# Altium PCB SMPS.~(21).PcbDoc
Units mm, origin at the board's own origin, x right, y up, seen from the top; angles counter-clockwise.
Board outline 100 x 80 mm, 2 copper layers (Top Layer, Bottom Layer); 139 components, 61 nets, 425 pads, 31 vias.
Unrouted connection lines stored in the file: 313.
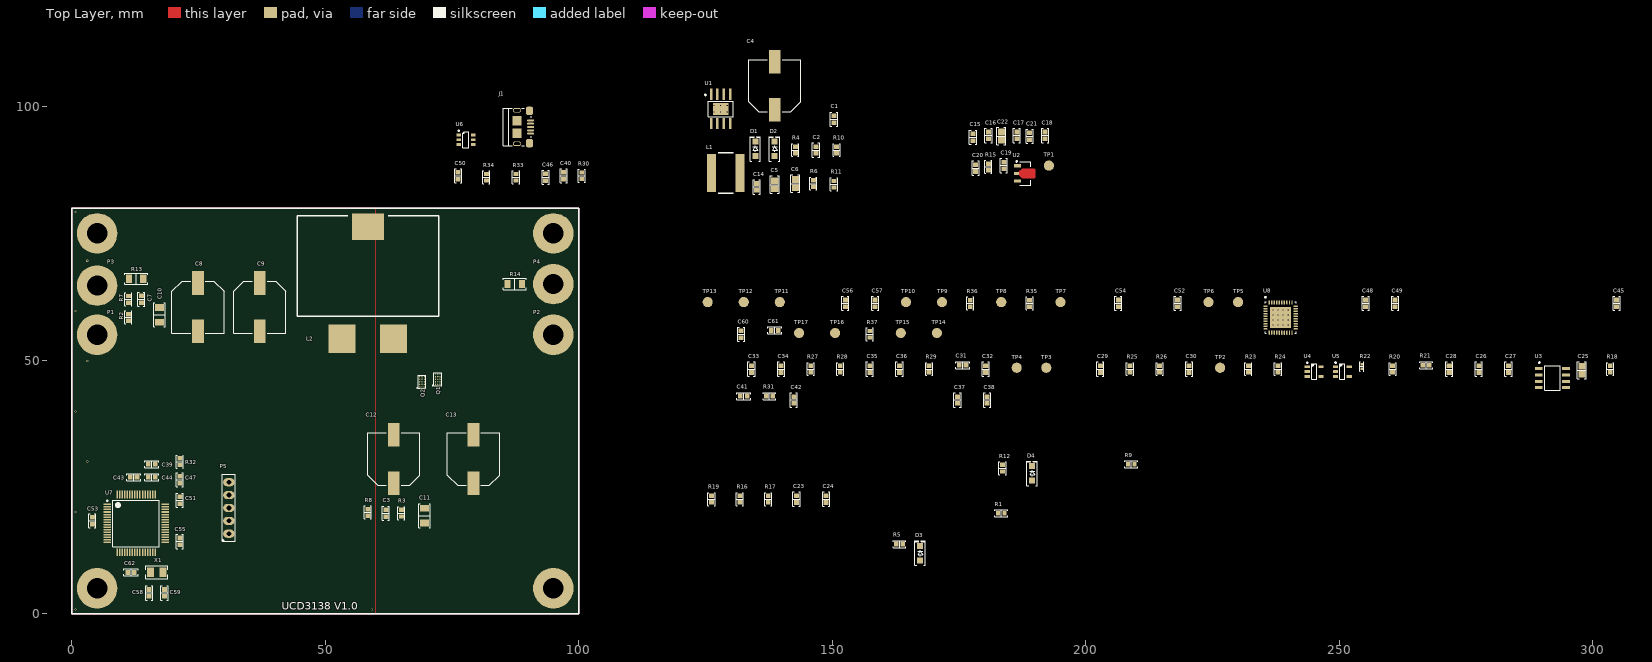
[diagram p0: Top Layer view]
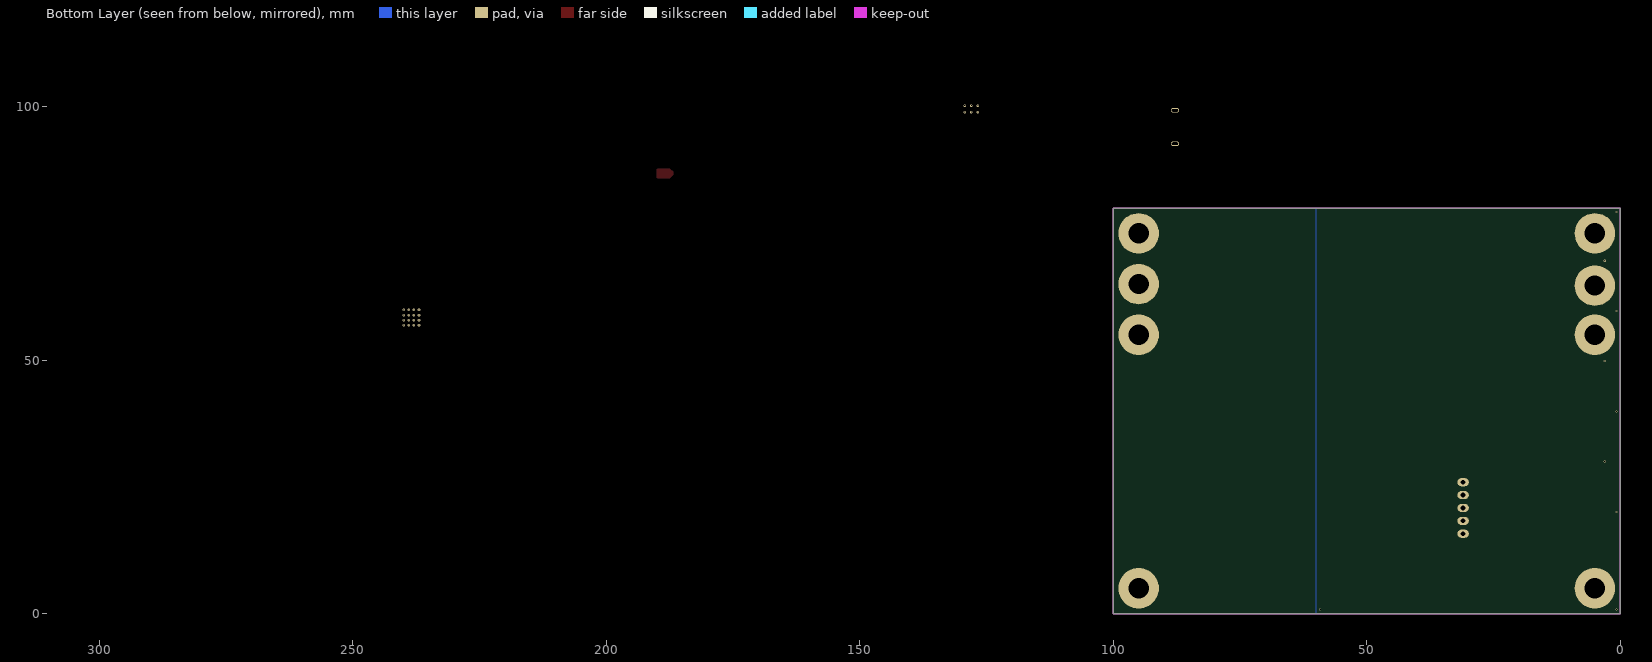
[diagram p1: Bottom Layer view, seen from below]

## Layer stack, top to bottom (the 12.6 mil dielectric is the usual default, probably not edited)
Top Solder: solder mask 0.0102, Solder Resist, Dk 3.5
Top Layer: signal copper 0.0356
Dielectric 1: dielectric 0.32, FR-4, Dk 4.8
Bottom Layer: signal copper 0.0356
Bottom Solder: solder mask 0.0102, Solder Resist, Dk 3.5

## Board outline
0,0 0,80 100,80 100,0

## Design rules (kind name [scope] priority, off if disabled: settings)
Clearance [All] p1: gap=0.254 ignorepadtopadclearanceinfootprint=FALSE except(0: Arc-Hole Track-Hole SMDPad-Hole THPad-Hole Via-Hole Fill-Hole Poly-Hole Region-Hole Text-Hole; 0.178: SMDPad-SMDPad; 0.203: Track-SMDPad; 0.229: Arc-Arc Arc-Track Arc-SMDPad Track-Track; 0.508: THPad-THPad)
ComponentClearance U1 [InComponent('U1')] p1: gap=0.508 collisioncheckmode=3 verticalgap=0 showdistances=TRUE
ComponentClearance [All] p2: gap=0.5 collisioncheckmode=3 verticalgap=0.1 showdistances=TRUE
Height [All] p1: minheight=0 maxheight=50.8 prefheight=12.7
HoleSize [All] p1: absolutevalues=TRUE maxlimit=10 minlimit=0.2 maxpercent=80.000 minpercent=20.000
MinimumSolderMaskSliver [All] p1: minsoldermaskwidth=0.025
PlaneClearance [All] p1: clearance=0.254
PlaneConnect [All] p1: planeconnectstyle=Direct reliefexpansion=0.508 reliefentries=4 reliefconductorwidth=0.508 reliefairgap=0.508
PolygonConnect GND [InNet('GND')] p1: connectstyle=Direct reliefconductorwidth=0.254 reliefentries=4 polygonreliefangle="90 Angle" airgapwidth=0.254
PolygonConnect DirectConnect [All] p2: connectstyle=Direct reliefconductorwidth=0.254 reliefentries=4 polygonreliefangle="90 Angle" airgapwidth=0.254
RoutingVias [All] p1: holewidth=0.2 width=0.8 viastyle="Through Hole" minholewidth=0.2 minwidth=0.4 maxholewidth=0.4 maxwidth=0.8
SilkToSilkClearance [All] p1: silktosilkclearance=0
SolderMaskExpansion [All] p1: expansion=0.102
Width [All] p1: maxlimit=12.7 minlimit=0.254 preferedwidth=0.254
23 further rules are at their usual default settings.

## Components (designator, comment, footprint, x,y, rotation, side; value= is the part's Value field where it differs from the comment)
C1 "10nF" C0603 150.368,97.536 r90 top
C2 "1nF" C0603 146.812,91.44 r90 top
C3 "10nF" C0603 61.976,19.812 r270 top
C4 "47µF 80V" "CAP ALUM 10.3MM" 138.684,104.14 r90 top
C5 "10µF 16V" C0805 138.684,84.62 r90 top
C6 "10µF 16V" C0805 142.748,84.836 r90 top
C7 "10nF" C0603 13.716,61.976 r270 top
C8 "47µF 80V" "CAP ALUM 10.3MM" 24.892,60.452 r270 top
C9 "47µF 80V" "CAP ALUM 10.3MM" 37.084,60.452 r270 top
C10 "1µF 80V" C1206 17.272,58.928 r270 top
C11 "1µF 80V" C1206 69.596,19.304 r270 top
C12 "47µF 80V" "CAP ALUM 10.3MM" 63.5,30.48 r90 top
C13 "47µF 80V" "CAP ALUM 10.3MM" 79.248,30.48 r90 top
C14 "47pF" C0603 135.128,84.161 r90 top
C15 "10µF" C0603 177.8,93.98 r90 top
C16 "100nF" C0603 180.848,94.321 r90 top
C17 "10nF" C0603 186.436,94.321 r90 top
C18 "10µF" C0603 192.024,94.321 r90 top
C19 "100nF" C0603 183.896,88.392 r90 top
C20 "10nF" C0603 178.308,87.884 r90 top
C21 "100nF 16V" C0603 188.976,94.147 r90 top
C22 "1µF 16V" C0805 183.388,94.196 r90 top
C23 "22pF" C0603 142.974,22.578 r90 top
C24 "22pF" C0603 148.816,22.578 r90 top
C25 "10µF 16V" C0805 297.914,47.978 r90 top
C26 "33pF" C0603 277.594,48.232 r90 top
C27 "33pF" C0603 283.436,48.232 r90 top
C28 "1µF 16V" C0603 271.752,48.232 r90 top
C29 "22pF" C0603 202.918,48.232 r90 top
C30 "22pF" C0603 220.444,48.232 r90 top
C31 "1µF" C0603 175.74,48.994 r0 top
C32 "1µF" C0603 180.312,48.232 r90 top
C33 "100nF" C0603 134.084,48.232 r90 top
C34 "22pF" C0603 139.926,48.232 r90 top
C35 "22pF" C0603 157.452,48.232 r90 top
C36 "100nF" C0603 163.294,48.232 r90 top
C37 "4.7µF" C0603 174.724,42.136 r90 top
C38 "4.7µF" C0603 180.566,42.136 r90 top
C39 "4.7µF" C0603 15.748,29.464 r180 top
C40 "47pF" C0603 97.056,86.36 r90 top
C41 "10nF" C0603 132.56,42.898 r0 top
C42 "10nF" C0603 142.466,42.136 r90 top
C43 "100nF" C0603 12.192,26.924 r180 top
C44 "100nF" C0603 15.748,26.924 r180 top
C45 "1µF" C0603 304.772,61.186 r90 top
C46 "10nF" C0603 93.472,86.078 r90 top
C47 "100nF" C0603 21.336,26.416 r90 top
C48 "2.2µF" C0603 255.242,61.186 r90 top
C49 "10nF" C0603 261.084,61.186 r90 top
C50 "47pF" C0603 76.228,86.36 r90 top
C51 "100nF" C0603 21.336,22.352 r90 top
C52 "1nF" C0603 218.158,61.186 r90 top
C53 "100nF" C0603 4.064,18.288 r90 top
C54 "1nF" C0603 206.474,61.186 r90 top
C55 "100nF" C0603 21.336,14.224 r90 top
C56 "33pF" C0603 152.626,61.186 r90 top
C57 "33pF" C0603 158.468,61.186 r90 top
C58 "26pF" C0603 15.24,4.064 r90 top
C59 "26pF" C0603 18.288,4.064 r90 top
C60 "2.2µF" C0603 132.052,55.09 r90 top
C61 "1µF" C0603 138.656,55.852 r0 top
C62 "1µF" C0603 11.684,8.128 r180 top
D1 "DSS120UTR" SOD123F 134.846,91.666 r90 top
D2 "DSS120UTR" SOD123F 138.656,91.666 r90 top
D3 "DSS120UTR" SOD123F 167.358,11.91 r90 top
D4 "DSS120UTR" SOD123F 189.456,27.658 r90 top
J1 "10118192-0001LF" "FCI USB 10118193-0001LF" 87.884,95.984 r90 top
L1 "NR8040T220M" SELF_SMD_8x8 129.032,86.868 r0 top
L2 "PQ2617BHA-220K" SELF_SMD_PQ2617 58.42,68.58 r0 top
P1 "PTH" HOLE_4 5,55 r0 top
P2 "PTH" HOLE_4 95,55 r0 top
P3 "PTH" HOLE_4 5,64.703 r0 top
P4 "PTH" HOLE_4 95,65 r0 top
P5 "5x2.54" "SAMTEC SSW-105-03-T-S" 30.988,20.828 r90 top
Q1 "EPC2045" EPC2045 72.194,46.228 r90 top
Q2 "EPC2045" EPC2045 69.088,45.72 r90 top
R1 "5R11" R0603 183.36,19.784 r0 top
R2 "21.5k 0.1%" R0603 11.176,58.42 r90 top
R3 "21.5k 0.1%" R0603 65.024,19.812 r270 top
R4 "249k" R0603 142.748,91.44 r90 top
R5 "10k" R0603 163.294,13.688 r0 top
R6 "91k" R0603 146.304,84.836 r90 top
R7 "1k 0.1%" R0603 11.176,61.976 r90 top
R8 "1k 0.1%" R0603 58.42,19.954 r90 top
R9 "5R11" R0603 209.014,29.436 r0 top
R10 "30.1k" R0603 150.876,91.44 r90 top
R11 "10k" R0603 150.368,84.694 r90 top
R12 "10k" R0603 183.614,28.674 r90 top
R13 "1m 1% 1W 50ppm" R1206 12.7,66.04 r180 top
R14 "1m 1% 1W 50ppm" R1206 87.376,65.024 r180 top
R15 "1R" R0603 180.82,88.11 r90 top
R16 "1k" R0603 131.798,22.578 r90 top
R17 "1k" R0603 137.386,22.578 r90 top
R18 "301k 0.1%" R0603 303.502,48.232 r90 top
R19 "301k 0.1%" R0603 126.21,22.578 r90 top
R20 "1k 0.1%" R0603 260.576,48.232 r90 top
R21 "1k 0.1%" R0603 267.18,48.994 r0 top
R22 "10k CTN" "NTC 0402/1005" 254.48,48.74 r90 top
R23 "1k" R0603 232.128,48.232 r90 top
R24 "1k" R0603 237.97,48.232 r90 top
R25 "1k 0.1%" R0603 208.76,48.232 r90 top
R26 "1k 0.1%" R0603 214.602,48.232 r90 top
R27 "301k 0.1%" R0603 145.768,48.232 r90 top
R28 "301k 0.1%" R0603 151.61,48.232 r90 top
R29 "10k" R0603 169.136,48.232 r90 top
R30 "27R" R0603 100.612,86.36 r90 top
R31 "1R" R0603 137.64,42.898 r0 top
R32 "10k" R0603 21.336,29.972 r90 top
R33 "1M" R0603 87.63,86.078 r90 top
R34 "27R" R0603 81.788,86.078 r90 top
R35 "100" R0603 188.948,61.186 r90 top
R36 "100" R0603 177.264,61.186 r90 top
R37 "2.2k" R0603 157.452,55.09 r90 top
TP1 "Test Point" "Test Point" 192.758,88.364 r0 top
TP2 "Test Point" "Test Point" 226.54,48.486 r0 top
TP3 "Test Point" "Test Point" 192.25,48.486 r0 top
TP4 "Test Point" "Test Point" 186.408,48.486 r0 top
TP5 "Test Point" "Test Point" 230.096,61.44 r0 top
TP6 "Test Point" "Test Point" 224.254,61.44 r0 top
TP7 "Test Point" "Test Point" 195.044,61.44 r0 top
TP8 "Test Point" "Test Point" 183.36,61.44 r0 top
TP9 "Test Point" "Test Point" 171.676,61.44 r0 top
TP10 "Test Point" "Test Point" 164.564,61.44 r90 top
TP11 "Test Point" "Test Point" 139.672,61.44 r90 top
TP12 "Test Point" "Test Point" 132.56,61.44 r90 top
TP13 "Test Point" "Test Point" 125.448,61.44 r90 top
TP14 "Test Point" "Test Point" 170.66,55.344 r90 top
TP15 "Test Point" "Test Point" 163.548,55.344 r90 top
TP16 "Test Point" "Test Point" 150.594,55.344 r90 top
TP17 "Test Point" "Test Point" 143.482,55.344 r90 top
U1 "LM5164" R-PDSO-G8 128.016,99.568 r0 top
U2 "AP7381-33Y-13" "ON SEMI SOT-89 H" 187.932,86.84 r0 top
U3 "MIC4605-1YM" SOIC-8 292.072,46.454 r0 top
U4 "LMV793" "TI SOT-23-5 DBV" 245.082,47.724 r0 top
U5 "LMV793" "TI SOT-23-5 DBV" 250.67,47.724 r0 top
U6 "IP4234CZ6" "VISHAY TSOP-6 MO-193C" 77.752,93.472 r0 top
U7 "ATSAME51J20A" TQFP-64N 12.7,17.78 r0 top
U8 "UCD3138RHAR" S-PVQFN-N40 238.478,58.392 r0 top
X1 "32.768kHz" "ABRACON ABS07" 16.764,8.128 r0 top

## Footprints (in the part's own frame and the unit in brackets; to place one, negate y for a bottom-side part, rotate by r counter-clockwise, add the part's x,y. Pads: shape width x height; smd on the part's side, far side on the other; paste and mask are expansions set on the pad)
"ABRACON ABS07" [mm] "Crystal, 2-Leads, Body 3.20x1.50mm, IPC Medium Density"
  rect 1.4x1.9 smd: 1(-1.2,0) 2(1.2,0)
  silkscreen extent -2.2,-1.3 2.2,1.3, body extent -1.62,-0.77 1.63,0.78, height 0.9
C0603 [mm] "Chip Capacitor, 2-Leads, Body 1.60x0.80mm, IPC Medium Density"
  rect 0.9x1 smd: 1(-0.675,0) 2(0.675,0)
  silkscreen extent -1.4,-0.7 1.4,0.7, body extent -0.8,-0.41 0.8,0.41, height 0.82
C0805 [mm] "Chip Capacitor, 2-Leads, Body 2.00x1.20mm, IPC Medium Density"
  rect 1.3x1.4 smd: 1(-0.8,0) 2(0.8,0)
  silkscreen extent -1.7,-0.9 1.7,0.9, body extent -1,-0.64 1,0.64, height 1.26
C1206 [mm] "Chip Capacitor, 2-Leads, Body 3.25x1.60mm, IPC Medium Density"
  rect 1.3x1.8 smd: 1(-1.45,0) 2(1.45,0)
  silkscreen extent -2.37,-1.12 2.37,1.12, body extent -1.6,-0.81 1.6,0.81, height 1.62
"CAP ALUM 10.3MM" [mm] "Aluminum Electrolytic Capacitor, Body 10.30x10.30x10.50mm, IPC Low Density"
  rect 4.65x2.3 smd: 1(-4.75,0) 2(4.75,0)
  silkscreen extent -5.15,-5.15 5.15,5.15, body extent -5.8,-5.15 5.8,5.15, height 10.5
EPC2045 [mm] "EPC2045 GaNFet"
  round 0.23 smd: 1(-1,0.45) 2(-1,-0.45) 2(-1,0) 2(0,0) 2(0,0.45) 2(0,-0.45) 2(1,-0.45) 2(1,0) 2(1,0.45) 3(-0.5,-0.45) 3(-0.5,0) 3(-0.5,0.45) 3(0.5,-0.45) 3(0.5,0) 3(0.5,0.45)
  silkscreen extent -1.3,-0.75 1.25,1.05, body extent -1.25,-0.75 1.25,0.75, height 0.68
"FCI USB 10118193-0001LF" [mm] "USB 2.0 Type B Micro"
  oval 0.4x1.35 smd: 1(1.3,-2.625) 2(0.65,-2.625) 3(0,-2.625) 4(-0.65,-2.625) 5(-1.3,-2.625)
  oval 0.9x1.6 hole 0.5 slot 1.2 at 90 deg: S(-3.3,0.05) S(3.3,0.05)
  rrect50% 1.6x1.4 smd: S(-3.2,-2.4) S(3.2,-2.4)
  rect 1.9x1.8 smd: S(-1.2,0.05) S(1.2,0.05)
  silkscreen extent -3.7,-2.8 3.7,2.8, body extent -3.93,-2.9 3.93,2.76, height 2.78
HOLE_4 [mm] "Hole for M4 screw"
  round 8 hole 4: 1(0,0)
"NTC 0402/1005" [mm] "Chip Thermistor, 2-Leads, Body 1.00x0.50mm, IPC Medium Density"
  rect 0.5x0.55 smd: 1(-0.45,0) 2(0.45,0)
  silkscreen extent -0.9,-0.4 0.9,0.4, body extent -0.5,-0.26 0.5,0.26, height 0.52
"ON SEMI SOT-89 H" [mm] "SOT89, 3-Leads, Body 4.50x2.50mm, Pitch 1.50mm, Lead Span 3.3mm, IPC Medium Density"
  rect 1.4x0.6 smd: 1(-1.4,1.5) 3(-1.4,-1.5)
  rect 1x0.6 smd: 2(-1.6,0)
  Top Layer region: -1.1,0.3 -0.45,0.95 1.975,0.95 2.1,0.825 2.1,-0.825 1.975,-0.95 -0.45,-0.95 -1.1,-0.3
  silkscreen extent -1.65,-2.3 1.25,2.47, body extent -2.05,-2.25 2.1,2.25, height 1.5
R0603 [mm] "Chip Resistor, 2-Leads, Body 1.60x0.80mm, IPC Medium Density"
  rect 0.85x0.95 smd: 1(-0.65,0) 2(0.65,0)
  silkscreen extent -1.27,-0.7 1.27,0.7, body extent -0.8,-0.4 0.8,0.4, height 0.45
R1206 [mm] "Chip Resistor, 2-Leads, Body 3.13x1.55mm, IPC Medium Density"
  rect 1.2x1.65 smd: 1(-1.4,0) 2(1.4,0)
  silkscreen extent -2.3,-1.1 2.3,1.1, body extent -1.57,-0.8 1.62,0.8, height 0.6
R-PDSO-G8 [mm] "SOIC, 8-Leads, Body 4,90x3,90mm, Pitch 1,27mm, Thermal Pad 3,10x2,40mm, IPC Medium Density"
  rect 0.5x2.2 smd: 1(-1.905,2.875) 2(-0.635,2.875) 3(0.635,2.875) 4(1.905,2.875) 5(1.905,-2.875) 6(0.635,-2.875) 7(-0.635,-2.875) 8(-1.905,-2.875)
  rect 3.1x2.4 smd paste+0: 9(0,0)
  silkscreen extent -3.12,-1.52 2.5,2.87, body extent -2.5,-2 2.5,2, height 1.7
S-PVQFN-N40 [mm] "VQFN, 40-Leads, Body 6,00x6,00mm, Pitch 0,50mm, Thermal Pad 4,92x4,92mm, IPC Medium Density"
  oval 0.85x0.28 smd: 1(-2.975,2.25) 2(-2.975,1.75) 3(-2.975,1.25) 4(-2.975,0.75) 5(-2.975,0.25) 6(-2.975,-0.25) 7(-2.975,-0.75) 8(-2.975,-1.25) 9(-2.975,-1.75) 10(-2.975,-2.25) 21(2.975,-2.25) 22(2.975,-1.75) 23(2.975,-1.25) 24(2.975,-0.75) 25(2.975,-0.25) 26(2.975,0.25) 27(2.975,0.75) 28(2.975,1.25) 29(2.975,1.75) 30(2.975,2.25)
  oval 0.28x0.85 smd: 11(-2.25,-2.975) 12(-1.75,-2.975) 13(-1.25,-2.975) 14(-0.75,-2.975) 15(-0.25,-2.975) 16(0.25,-2.975) 17(0.75,-2.975) 18(1.25,-2.975) 19(1.75,-2.975) 20(2.25,-2.975) 31(2.25,2.975) 32(1.75,2.975) 33(1.25,2.975) 34(0.75,2.975) 35(0.25,2.975) 36(-0.25,2.975) 37(-0.75,2.975) 38(-1.25,2.975) 39(-1.75,2.975) 40(-2.25,2.975)
  rect 4.15x4.15 smd paste-2.075: 41(0,0)
  silkscreen extent -3.12,-3.08 3.08,4.12, body extent -3.08,-3.08 3.08,3.08, height 1
"SAMTEC SSW-105-03-T-S" [mm]
  oval 1.6x2.25 hole 0.95: 1(-5.08,0) 2(-2.54,0) 3(0,0) 4(2.54,0) 5(5.08,0)
  silkscreen extent -6.61,-1.27 6.61,1.27, body extent -6.6,-1.21 6.6,1.21, height 8.51
SELF_SMD_8x8 [mm] "Self SMD 8x8mm"
  rect 1.8x7.5 smd: 1(-2.8,0) 2(2.8,0)
  silkscreen extent -1.5,-4 1.5,4, body extent -4,-4 4,4, height 3
SELF_SMD_PQ2617 [mil] "Bourns shielded power inductor PQ2617"
  rect 210x220 smd: 1(-200,-565) 2(200,-565)
  rect 250x208 smd: 3(0,304)
  silkscreen extent -549,-390 549,390, body extent -549,-433 549,433, height 748
SOD123F [mm] "SODFL, 2-Leads, Body 1.60x3.50mm, IPC Medium Density"
  rect 1.2x1.2 smd: 1(-1.43,0) 2(1.43,0)
  silkscreen extent -2.41,-1.02 2.41,1.02, body extent -1.75,-0.8 1.75,0.8, height 1.1
SOIC-8 [mm] "8-Pin Plastic Narrow Body Small Outline Integrated Circuit 1.27 mm Pitch, IPC Medium Density"
  rect 1.5x0.6 smd: 1(-2.7,1.905) 2(-2.7,0.635) 3(-2.7,-0.635) 4(-2.7,-1.905) 5(2.7,-1.905) 6(2.7,-0.635) 7(2.7,0.635) 8(2.7,1.905)
  silkscreen extent -2.66,-2.45 1.52,3.17, body extent -1.95,-2.45 1.95,2.45, height 1.76
"Test Point" [mm] "Test Point"
  round 2 smd: 1(0,0)
"TI SOT-23-5 DBV" [mm] "SOT23, 5-Leads, Body 2.90x2.80mm, Pitch 0.95mm, IPC Medium Density"
  rect 1x0.55 smd: 1(-1.35,0.95) 2(-1.35,0) 3(-1.35,-0.95) 4(1.35,-0.95) 5(1.35,0.95)
  silkscreen extent -1.47,-1.55 0.5,1.9, body extent -1.44,-1.43 1.39,1.48, height 1.5
TQFP-64N [mm] "TSQFP, 64-Leads, Body 10,00x10,00mm, Pitch 0,50mm, IPC Medium Density"
  rect 1.5x0.3 smd: 1(-5.7,3.75) 2(-5.7,3.25) 3(-5.7,2.75) 4(-5.7,2.25) 5(-5.7,1.75) 6(-5.7,1.25) 7(-5.7,0.75) 8(-5.7,0.25) 9(-5.7,-0.25) 10(-5.7,-0.75) 11(-5.7,-1.25) 12(-5.7,-1.75) 13(-5.7,-2.25) 14(-5.7,-2.75) 15(-5.7,-3.25) 16(-5.7,-3.75) 33(5.7,-3.75) 34(5.7,-3.25) 35(5.7,-2.75) 36(5.7,-2.25) 37(5.7,-1.75) 38(5.7,-1.25) 39(5.7,-0.75) 40(5.7,-0.25) 41(5.7,0.25) 42(5.7,0.75) 43(5.7,1.25) 44(5.7,1.75) 45(5.7,2.25) 46(5.7,2.75) 47(5.7,3.25) 48(5.7,3.75)
  rect 0.3x1.5 smd: 17(-3.75,-5.7) 18(-3.25,-5.7) 19(-2.75,-5.7) 20(-2.25,-5.7) 21(-1.75,-5.7) 22(-1.25,-5.7) 23(-0.75,-5.7) 24(-0.25,-5.7) 25(0.25,-5.7) 26(0.75,-5.7) 27(1.25,-5.7) 28(1.75,-5.7) 29(2.25,-5.7) 30(2.75,-5.7) 31(3.25,-5.7) 32(3.75,-5.7) 49(3.75,5.7) 50(3.25,5.7) 51(2.75,5.7) 52(2.25,5.7) 53(1.75,5.7) 54(1.25,5.7) 55(0.75,5.7) 56(0.25,5.7) 57(-0.25,5.7) 58(-0.75,5.7) 59(-1.25,5.7) 60(-1.75,5.7) 61(-2.25,5.7) 62(-2.75,5.7) 63(-3.25,5.7) 64(-3.75,5.7)
  silkscreen extent -5.82,-4.6 4.6,4.6, body extent -5,-5 5,5, height 1.2
"VISHAY TSOP-6 MO-193C" [mm] "SOT23, 6-Leads, Body 3.03x2.84mm, Pitch 0.95mm, IPC Medium Density"
  rect 0.85x0.55 smd: 1(-1.425,0.95) 2(-1.425,0) 3(-1.425,-0.95) 4(1.425,-0.95) 5(1.425,0) 6(1.425,0.95)
  silkscreen extent -1.55,-1.55 0.6,1.9, body extent -1.44,-1.52 1.44,1.53, height 1.45

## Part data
C1 C2 C3 C4 C5 C6 C7 C8 C9 C10 C11 C12 C13 C14 C15 C16 C17 C18 C19 C20 C21 C22 C23 C24 C25 C26 C27 C28 C29 C30 C31 C32 C33 C34 C35 C36 C37 C38 C39 C40 C41 C42 C43 C44 C45 C46 C47 C48 C49 C50 C51 C52 C53 C54 C55 C56 C57 C58 C59 C60 C61 C62: library part Cap, "Capacitor"
D1 D2 D3 D4: library part "D Schottky", "Schottky Diode"
J1: library part 1-353576-1, "USB 1.1, Right Angle, SMT, A Type, Receptacle, 4 Position, White"
L1 L2: library part "Inductor Iron", "Magnetic-Core Inductor"
P1 P2 P3 P4: "Plated Trough Hole for screew"
P5: library part "Header 5", "Header, 5-Pin"
Q1 Q2: library part MOSFET_N
R1 R2 R3 R4 R5 R6 R7 R8 R9 R10 R11 R12 R13 R14 R15 R16 R17 R18 R19 R20 R21 R23 R24 R25 R26 R27 R28 R29 R30 R31 R32 R33 R34 R35 R36 R37: library part Res2, "Resistor"
R22: library part "Res Varistor", "Varistor (Voltage-Sensitive Resistor)"
U1: "100-V Input, 1-A synchronous buck DC/DC converter with ultra-low IQ"
U2: library part "Volt Reg", "Voltage Regulator"
U3: "85V Half-Bridge MOSFET Driver with Adaptive Dead Time  and Shoot-Through Protection"
U4 U5: library part "AOP - 1"
U6: "Single USB 2.0 ESD protection to IEC 61000-4-2 level 4"
U8: "Highly Integrated Digital Controller for Isolated Power with 3 Feedback Loops and 8 DPWM Outputs, 40pins"
X1: library part XTAL, "Crystal Oscillator"

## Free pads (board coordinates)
  round 8 hole 4: 1(5,5) 1(5,75) 1(95,5) 1(95,75)

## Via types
v1: diameter 0.5, hole 0.2, Top Layer to Bottom Layer, 22 vias
v2: diameter 0.4, hole 0.2, Top Layer to Bottom Layer, 9 vias

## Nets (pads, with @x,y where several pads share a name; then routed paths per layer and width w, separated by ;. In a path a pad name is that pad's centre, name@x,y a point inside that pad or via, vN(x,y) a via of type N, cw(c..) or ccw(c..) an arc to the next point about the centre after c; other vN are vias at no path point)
+3.3V: C15.1 C16.1 C17.1 C38.1 C42.1 C43.2 C48.2 C51.2 C53.1 C55.2 C62.2 P5.1 R15.2 R31.1 R32.2 U2.3 U7.8 U7.21 U7.34 U7.48 U7.56 U8.27
+3.3Vana: C18.1 C19.1 C20.1 C33.1 C36.1 R15.1 R22.2 TP1.1 U4.5 U5.5
+12V: C2.2 C5.1 C6.1 C21.1 C22.1 C25.2 L1.2 R6.1 U2.1 U3.1
+Vbus: C8.2 C9.2 C10.2 D1.1 L2.1 P1.1 R2.1
+Vcells: C11.2 C12.2 C13.2 D2.1 P2.1 Q1.3 R3.1
ALERT: TP9.1 U7.19 U8.19
Ccells: C28.1 L2.2 Q1.2 Q2.3 R5.2 TP3.1 U3.4
CTRL: TP10.1 U7.20 U8.20
DPWM0A: TP5.1 U3.5 U8.11
DPWM0B: TP6.1 U3.6 U8.12
GND: C4.1 C5.2 C6.2 C8.1 C9.1 C10.1 C11.1 C12.1 C13.1 C15.2 C16.2 C17.2 C18.2 C19.2 C20.2 C21.2 C22.2 C25.1 C26.1 C27.1 C31.1 C32.1 C33.2 C34.1 C35.1 C36.2 C37.1 C38.2 C39.2 C40.1 C41.1 C42.2 C43.1 C44.2 C45.1 C46.2 C47.1 C49.1 C50.1 C51.1 C52.2 C53.2 C54.2 C55.1 C56.2 C57.2 C58.1 C59.1 C60.2 C61.2 C62.1 J1.5 P5.5 pad.1 Q2.2 R10.2 R11.2 R12.2 R13.1 R14.2 R25.1 R26.2 R27.2 R28.2 R29.2 R33.1 U1.1 U1.9 U2.2 U3.7 U4.2 U5.2 U7.7 U7.22 U7.33 U7.47 U7.54 U8.1 U8.6 U8.26 U8.29 U8.30 U8.32 U8.34 U8.36 U8.41
  other v1: 236.978,56.892 237.978,56.892 238.978,56.892 239.978,56.892 236.978,57.892 237.978,57.892 238.978,57.892 239.978,57.892 236.978,58.892 237.978,58.892 238.978,58.892 239.978,58.892 236.978,59.892 237.978,59.892 238.978,59.892 239.978,59.892 126.716,98.918 128.016,98.918 129.316,98.918 126.716,100.218 128.016,100.218 129.316,100.218
  other v2: 0.762,0.762 59.182,0.762 0.762,20.066 3.048,29.972 0.762,39.878 3.048,49.784 0.762,59.69 3.048,69.596 0.762,79.248
Hcells: D3.2 R1.1 TP2.1 U3.3
Ibus_peak: C26.2 R16.2 TP13.1 U8.40
Ibus_sense: C31.2 R23.2 TP12.1 U8.39
Icells_peak: C27.2 R17.1 TP16.1 U8.3
Icells_sense: C32.2 R24.1 TP15.1 U8.4 U8.35
Lcells: D4.2 R9.1 TP4.1 U3.8
NetC1_1: C1.1 L1.1 R4.1 U1.8
NetC1_2: C1.2 U1.7
NetC2_1: C2.1 C14.2 R4.2
NetC4_2: C4.2 D1.2 D2.2 U1.2 U1.3
NetC14_1: C14.1 R6.2 R11.1 U1.5
NetC23_1: C23.1 R16.1 R18.2 R23.1 U4.1
NetC23_2: C23.2 C29.2 R18.1 R20.2 U4.4
NetC24_1: C24.1 C30.2 R19.2 R21.1 U5.4
NetC24_2: C24.2 R17.2 R19.1 R24.2 U5.1
NetC28_2: C28.2 U3.2
NetC29_1: C29.1 C34.2 R25.2 R27.1 U4.3
NetC30_1: C30.1 C35.2 R26.1 R28.1 U5.3
NetC37_2: C37.2 C41.2 R31.2 U8.37
NetC39_1: C39.1 C44.1 U7.53
NetC40_2: C40.2 R30.2 U6.6
NetC45_2: C45.2 C48.1 C49.2 U8.28
NetC46_1: C46.1 J1.S R33.2 U6.2
NetC50_2: C50.2 R34.2 U6.1
NetC56_1: C56.1 R35.1 U8.9
NetC57_1: C57.1 R36.1 U8.10
NetC58_2: C58.2 U7.31 X1.1
NetC59_2: C59.2 U7.32 X1.2
NetC60_1: C60.1 R37.1 U8.7
NetD3_1: D3.1 Q1.1 R1.2 R5.1
NetD4_1: D4.1 Q2.1 R9.2 R12.1
NetJ1_1: J1.1 U6.5
NetJ1_2: J1.2 U6.4
NetJ1_3: J1.3 U6.3
NetR10_1: R10.1 U1.4
R\S\T\: C47.2 P5.4 R32.1 U7.52
Rbus: C7.1 P3.1 R7.2 R13.2 R20.1
Rcells: C3.1 P4.1 R8.2 R14.1 R21.2
SCL: R35.2 TP7.1 U7.18
SDA: R36.2 TP8.1 U7.17
SMPS_R\E\S\E\T\: C61.1 R37.2 U7.16
SWCLK: U7.59
SWDCLK: P5.3
SWDIO: P5.2 U7.60
SYNC: U8.8
Temp: R22.1 R29.1 TP17.1 U8.2
"USB D+": R34.1 U7.46
"USB D-": R30.1 U7.45
Vbus_sense: C7.2 C52.1 R2.2 R7.1 TP11.1 U8.31 U8.38
Vcells_sense: C3.2 C54.1 R3.2 R8.1 TP14.1 U8.5 U8.33
pads on no net: J1.4 L2.3 U1.6 U7.1 U7.2 U7.3 U7.4 U7.5 U7.6 U7.9 U7.10 U7.11 U7.12 U7.13 U7.14 U7.15 U7.23 U7.24 U7.25 U7.26 U7.27 U7.28 U7.29 U7.30 U7.35 U7.36 U7.37 U7.38 U7.39 U7.40 U7.41 U7.42 U7.43 U7.44 U7.49 U7.50 U7.51 U7.55 U7.57 U7.58 U7.61 U7.62 U7.63 U7.64 U8.13 U8.14 U8.15 U8.16 U8.17 U8.18 U8.21 U8.22 U8.23 U8.24 U8.25

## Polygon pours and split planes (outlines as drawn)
GND on Bottom Layer "GND_bottom" (solid, shelved, pour order 72): 0,0 60,0 60,80 0,80
GND on Top Layer "GND_top" (solid, shelved, pour order 73): 0,0 60,0 60,80 0,80

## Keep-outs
Keep-Out Layer:
  the board outline again, w0.254

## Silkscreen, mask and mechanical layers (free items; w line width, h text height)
Top Overlay:
  the board outline again, w0.254
  text "UCD3138 V1.0" at 41.402,0.762 h1.52
Drill Drawing:
  the board outline again, w0.254

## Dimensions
0,-1 to 100,-2 on Mechanical 2
-1,0 to -1,80 on Mechanical 2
